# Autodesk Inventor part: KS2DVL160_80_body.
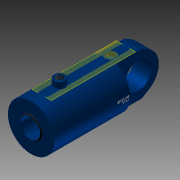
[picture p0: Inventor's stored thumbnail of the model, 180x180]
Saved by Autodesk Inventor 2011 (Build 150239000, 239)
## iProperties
Created: 2010-11
Document SubType Name: Modeling
Designer: TB
Mass: 405.061 g
Surface Area: 916.939 cm^2
Volume: 405.061 cm^3
Density: 1 g/cm^3
Author: TB
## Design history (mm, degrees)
sketch "Sketch2"
  geometry: L1 (-35, -3)-(-35, 3); L2 (-35, -9)-(-35, 9); L3 (-35, 0)-(-35, 92.5); L4 (-35, 92.5)-(-328, 92.5); L5 (-328, 92.5)-(-328, 92.5); L6 (-328, 92.5)-(-338, 92.5); L7 (-338, 92.5)-(-338, 44); L8 (-338, 44)-(-341, 41); L9 (-341, 41)-(-341, 40); L10 (-341, 40)-(-214, 40); L11 (-214, 40)-(-214, 80); L12 (-214, 80)-(-62, 80); L13 (-62, 80)-(-62, 0); L14 (-62, 0)-(-35, 0); L15 (-62, 0)-(-148.421, 0); L16 (-35, 9)-(-32, 12) reference; L17 (-32, 12)-(-35, 12) reference; L18 (-35, 12)-(-35, 9) reference; L19 (-32, 12)-(-35, 9) reference; L20 (-32, 12)-(-35, 12) reference; L21 (-35, 9)-(-35, 12) reference; L22 (-35, 9)-(-32, 12) reference; 1 further point
  constraints: 44 end point, 8 perpendicular, 6 parallel, 5 collinear, 2 horizontal, 2 vertical, 1 coincident, 1 midpoint, 1 point on line, 10 other
  dimensions: "DiaY" = 185 diameter of L4 L15; "DiaI" = 160 diameter of L12 L15; "d4" = 1 distance of L8.end L9.end; "d5" = 45 deg angle of L10 L8; "d6" = 3 distance between parallel lines of L7 L9; "DiaStang" = 80 diameter of L10 L15; "RindDia" = 185 diameter of L6 L15; "RingLengde" = 10 distance of L5.end L6.end; "RingTykk" = 124 distance between parallel lines of L11 L7; "KroppLengde" = 303 distance between parallel lines of L7 L3 (derived); "BunnTykkelse" = 27 distance between parallel lines of L13 L3
revolve "Kropp" sketch "Sketch2" stored, may be unused: angle "d13" = 90 deg
sketch "Sketch3"
  geometry: L1 (-62, -80)-(-62, 80) reference; L2 (-62, 0.01)-(-162, 0.01); L3 (-162, -0.01)-(-62, -0.01); A1 r 0.01 centre (-162, 0) between (-162, 0.01) and (-162, -0.01); A2 r 0.01 centre (-62, 0) between (-62, -0.01) and (-62, 0.01); 2 further points
  constraints: 4 end point, 4 point on circle, 4 tangent, 2 centre point, 1 coincident, 1 midpoint, 1 parallel, 1 perpendicular
  dimensions: "d17" = 0.01 radius of A2; "d18" = 100 distance of L2.start L2.end (= Slaglengde)
feature "BaneTransitionalConstraint" sketch "Sketch3" dims "d19" = 2, "d20" = 0
sketch "Sketch6"
  geometry: L1 (-129.5, 0)-(129.5, 0) reference; L2 (16.591, 91)-(-11.843, 91); L3 (92.5, 0)-(92.5, 31.248); L4 (-92.5, 0)-(-92.5, -18.451); A1 r 92.5 centre (0, 0) between (-92.5, 0) and (92.5, 0) reference; 2 further points
  constraints: 6 end point, 2 point on circle, 2 vertical, 2 other
  dimensions: "d30" = 91 distance from line of point (0, 0) L2 (computed from DiaY); "d31" = 0 deg angle of L1 L2 (computed from Vinkel_Plussport); "d37" = 90 deg angle of L2 L3; "d38" = 90 deg angle of L2 L4
  node "Projected Loop3"
workplane "Work Plane5"
sketch "Sketch7"
  geometry: L1 (16.591, -409.2)-(16.591, 68.2) reference; L2 (-19.633, -35)-(38.367, -35) reference; C1 r 22.5 at (16.591, -52.5); 1 further point
  constraints: 1 centre point, 1 point on line
  dimensions: "PortDia" = 45 diameter of C1
extrude "Extrusion2" cut sketch "Sketch7" stored distance "d34" = 1.5; taper "d35" = 0 deg
workplane "Work Plane7"
sketch "Sketch4"
  geometry: L1 (-16.68, -40)-(-16.68, -78.777); L2 (-16.68, -78.777)-(16.68, -78.777); L3 (16.68, -78.777)-(16.68, -40); L4 (16.68, -40)-(-16.68, -40); L5 (-40.643, -40)-(0, -40); L6 (-29, -35)-(29, -35); L7 (0, -35)-(0, -40); 2 further points
  constraints: 6 end point, 2 midpoint, 2 other
  dimensions: "d40" = 5 distance of L7.start L5.end
emboss "Emboss1" sketch "Sketch4" dims "d4" = 1, "d5" = 45 deg, "d6" = 3, "d22" = 0.2, "d23" = 0, "DiaI" = 160, "DiaY" = 185, "RindDia" = 185, "DiaStang" = 80, "RingTykk" = 124, "RingLengde" = 10, "KroppLengde" = 303 (derived), "BunnTykkelse" = 27
workplane "Work Plane8"
sketch "Sketch8"
  geometry: L1 (-29, -35)-(29, -35); L2 (0, -35)-(0, -40); L3 (-5.906, -110.587)-(-5.906, -40); L4 (-5.906, -40)-(5.906, -40); L5 (5.906, -40)-(5.906, -110.587); L6 (5.906, -110.587)-(-5.906, -110.587); L7 (92.5, -35)-(-92.5, -35); L8 (92.5, -35)-(-92.5, -35) reference; 3 further points
  constraints: 6 end point, 4 midpoint, 2 other
  dimensions: "d42" = 5 distance of L2.start L2.end
emboss "Emboss2" sketch "Sketch8" dims "d4" = 1, "d5" = 45 deg, "d6" = 3, "d43" = 0.2, "d44" = 0, "DiaI" = 160, "DiaY" = 185, "RindDia" = 185, "DiaStang" = 80, "RingTykk" = 124, "RingLengde" = 10, "KroppLengde" = 303 (derived), "BunnTykkelse" = 27
sketch "Sketch9"
  geometry: A1 r 12.5 centre (9.367, -52.5) between (0, -60.776) and (18.735, -60.776) reference; 1 further point
hole "Hole1" sketch "Sketch9" at (9.367, -52.5) diameter "d45" = 14.95; stored, may be unused: countersink angle "d49" = 82 deg, drill point angle "d51" = 118 deg; dims "d46" = 6, "d47" = 3.023, "d48" = 2, "DiaInvPluss" = 30.5
workplane "Work Plane9"
sketch "Sketch10"
  geometry: L1 (-129.501, 0)-(129.501, 0) reference; L2 (0, 92.5)-(13.136, 92.5); L3 (0, 92.5)-(0, 31.79); L4 (22.5, 89.722)-(22.5, 115.5); L5 (22.5, 115.5)-(0, 115.5); L6 (0, 115.5)-(0, 92.5); L7 (0, 92.5)-(22.5, 89.722); C1 r 92.5 at (0, 0) reference; A1 r 92.5 centre (0, 0) between (0, 92.5) and (22.5, 89.722); 1 further point
  constraints: 12 end point, 4 perpendicular, 2 concentric, 2 point on circle, 1 centre point, 1 point on line, 1 tangent
  dimensions: "d53" = 0 deg angle of L1 L2 (computed from Vinkel_Minusport); "DiaUtvStussMinus" = 45 diameter of L4 L3; "HøydeStussMinuss" = 23 distance between parallel lines of L2 L5
revolve "Revolution2" sketch "Sketch10" stored, may be unused: angle "d56" = 90 deg
hole "Hole2" diameter "d59" = 30.291; stored, may be unused: countersink angle "d63" = 82 deg, drill point angle "d65" = 118 deg; dims "d57" = 10, "d58" = 10, "d60" = 6, "d61" = 3.023, "d62" = 2, "DiaInvStussMinus" = 30.5
fillet "Fillet1" dims "d66" = 2
sketch "Sketch15"
  geometry: L1 (35, -85.623)-(35, 85.623); L2 (-35, -85.623)-(-35, 85.623); L3 (0, 129.5)-(0, -129.5) reference; A1 r 92.5 centre (0, 0) between (35, -85.623) and (-35, -85.623) reference; A2 r 92.5 centre (0, 0) between (35, 85.623) and (-35, 85.623); A3 r 92.5 centre (0, 0) between (-35, -85.623) and (35, -85.623)
  constraints: 8 point on circle, 4 end point, 4 point on line, 2 centre point, 2 concentric, 2 parallel, 1 coincident
  dimensions: "EyeBunnTykk" = 35 distance from line of L1 A1.centre; "EyeBunnTykk2" = 35 distance from line of A1.centre L2
extrude "Extrusion6" join sketch "Sketch15" taper "d98" = 0 deg; distance "LengdeEyeMinussBunntykk" = 170
sketch "Sketch16"
  geometry: L1 (-337, 92.5)-(135, 92.5) reference; L2 (-337, -92.5)-(135, -92.5) reference; L3 (-337, 92.5)-(135, 92.5) reference; L4 (135, 92.5)-(135, 85.623) reference; L5 (135, -85.623)-(135, 85.623) reference; L6 (-422.9, 0)-(248.401, 0) reference; L7 (50.5, 92.5)-(135, 92.5); L8 (135, 92.5)-(135, 8); A1 r 84.5 centre (50.5, 8) between (135, 8) and (50.5, 92.5); 6 further points; 2 other entities
  constraints: 4 end point, 4 tangent, 2 point on circle, 2 point on line, 1 centre point, 1 collinear, 1 perpendicular, 2 other
  dimensions: "d137" = 8 distance from line of L8.end L6
extrude "Extrusion7" cut sketch "Sketch16" taper "d102" = 0 deg; stored distance "ExtruEyeBunn" = 70
mirror "Mirror1"
sketch "Sketch20"
  geometry: L1 (-337, 92.5)-(135, 92.5) reference; L2 (135, -85.623)-(135, 85.623) reference; L3 (135, 92.5)-(135, 85.623) reference; L4 (-420.681, 0)-(235.083, 0) reference; L5 (-35, -85.623)-(-35, 85.623) reference; L6 (-35, 0)-(55, 0); L7 (55, 0)-(55, 20.918); L8 (62.747, 88.481)-(96, 69.282); A1 r 35 centre (43.843, 57.5) between (43.843, 92.5) and (43.843, 92.5); A2 r 30 centre (47.747, 62.5) between (62.747, 88.481) and (47.747, 92.5); A3 r 80 centre (56, 0) between (135, 12.61) and (96, 69.282); 2 further points
  constraints: 7 point on line, 6 end point, 6 point on circle, 3 centre point, 2 tangent, 1 midpoint, 1 perpendicular
  dimensions: "d147" = 90 distance of L6.start L6.end; "d165" = 80 radius of A3; "d166" = 30 deg angle of L1 L8; "d167" = 30 radius of A2; "d169" = 1 distance of L6.end A3.centre
extrude "Extrusion10" cut sketch "Sketch20" stored distance "d144" = 10; taper "d145" = 0 deg
mirror "Mirror2"
sketch "Sketch17"
  geometry: L1 (171.245, 0)-(0, 0) reference; L2 (85.623, -401.2)-(85.623, 265.2) reference; C1 r 52.5 at (85.623, 90); 1 further point
  constraints: 1 centre point, 1 point on line
  dimensions: "DiaHullEyeBunn" = 105 diameter of C1; "d125" = 90 distance from line of C1.centre L1
extrude "Extrusion8" cut sketch "Sketch17" taper "d105" = 0 deg; distance "ExtruHullEye" = 70
pattern_circular "Circular Pattern1 Only Subsea" dims "d108" = 180 deg (derived)
workplane "Work Plane11"
sketch "Sketch18"
  geometry: L1 (0, -74.5)-(0, 13) reference; L2 (80, -62)-(-80, -62) reference; L3 (80, -62)-(-80, -62) reference; C1 r 22.5 at (0, -22); 1 further point
  constraints: 1 centre point
  dimensions: "DiaForsenkPlussPort" = 45 diameter of C1; "PlassPlussport" = 40 distance from line of L2 C1.centre
extrude "Extrusion9" cut sketch "Sketch18" stored distance "d113" = 10; taper "d114" = 0 deg
sketch "Sketch19"
  geometry: 8 further points
  constraints: 1 other
hole "Hole3" sketch "Sketch19" at (0, -22) diameter "d115" = 30.291; stored, may be unused: countersink angle "d119" = 90 deg, drill point angle "d121" = 118 deg; dims "d116" = 6, "d117" = 4, "d118" = 2, "d120" = 14.5
pattern_circular "Circular Pattern2 Only Subsea" dims angle "d123" = 360 deg
body "Solid1"
chamfer "Chamfer" distance "Chamfer" = 1; stored, may be unused: second distance "d15" = 2, angle "d16" = 45 deg
node "Projected Loop2"
body "Srf1"
node "Projected Loop10"
other parameters: "Slaglengde" = 100, "Forlengelse_rør" = 0, "Vinkel_Plussport" = 0 [user parameter; used in 1 equation term], "Vinkel_Minusport" = 0, "d32" = 90 deg, "d39" = 90 deg, "d41" = 90 deg, "PortMinusPlass" = -114, "Minusport2" = 180 deg, "ForsenkningPlussPort" = 90.7 (derived), "EyeLengdeUBunn" = 136, "d164" = 73
